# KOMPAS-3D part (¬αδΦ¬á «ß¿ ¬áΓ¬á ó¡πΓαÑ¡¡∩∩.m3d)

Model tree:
1. Эскиз:1
2. Операция выдавливания:1
     Расстояние 1 = 1
3. Эскиз:3
4. Отверстие:1
5. Эскиз:4
6. Операция выдавливания:3
     Расстояние 1 = 0.2
7. Массив по концентрической сетке:1  (with: Операция выдавливания:3)  (labels: Экземпляр ( 1, 1 ); Экземпляр ( 1, 2 ); Экземпляр ( 1, 3 ); Экземпляр ( 1, 4 ))
     N 2 = 6; Шаг 2 = 360
8. Эскиз:6
9. Операция выдавливания:5
     Расстояние 1 = 1
10. Массив по концентрической сетке:3  (with: Операция выдавливания:5)  (labels: Экземпляр ( 1, 1 ); Экземпляр ( 1, 2 ); Экземпляр ( 1, 3 ); Экземпляр ( 1, 4 ))
     N 2 = 6; Шаг 2 = 360
11. Скругление:5
     Радиус = 0.3
12. Скругление:6
     Радиус = 0.3
13. Скругление:7
     Радиус = 0.1

Referenced files in C:\Program Files\ASCON\KOMPAS-3D V13 Home\Sys\: holelib.lfr
Referenced files in C:\Program Files\ASCON\KOMPAS-3D V12\Sys\: holelib.lfr
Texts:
  крышка катка внутренняя
  крышка оси катка т90 наружняя для точеного
  Сплав АЛ8  ГОСТ 1583-93
  Отверстие 02
  (вариант 2)
  Номер 1
  Номер 2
